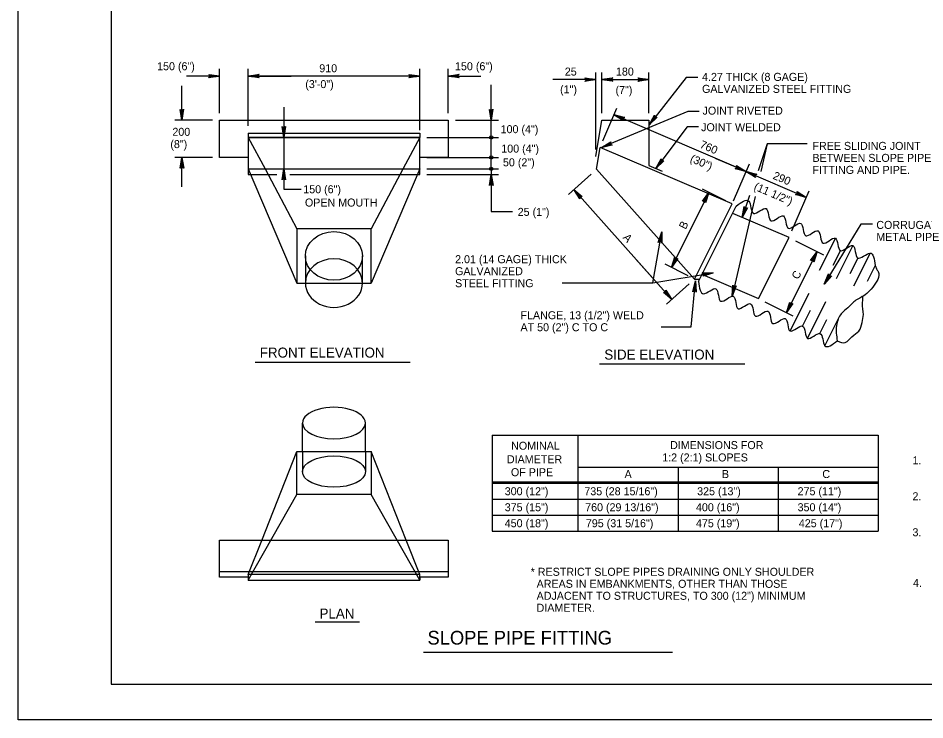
# Model space of a CAD drawing. Extents: x 637898 to 638802, y 298167 to 298761.
# Drawn here: x 637898 to 638278.7, y 298166.9 to 298461.7 of the extents above; entities that cross this region are included whole.
import ezdxf

# ---------------------------------------------------------------- set-up
doc = ezdxf.new("R2010")
doc.units = 0
for name, color, linetype in [('1', 7, 'Continuous'), ('2', 7, 'Continuous'), ('3', 7, 'Continuous'), ('PLT-BNDY', 7, 'Continuous')]:
    doc.layers.add(name, color=color, linetype=linetype)

msp = doc.modelspace()

# ---------------------------------------------------------------- linework, layer by layer
at = {"layer": '1'}
msp.add_lwpolyline([(638722.97, 298181.88), (638722.97, 298745.88), (637936.97, 298745.88), (637936.97, 298181.88), (638722.97, 298181.88), (638722.97, 298208.24), (638522.97, 298208.24), (638522.97, 298272.92), (638722.97, 298272.92), (638722.97, 298301.88), (638522.97, 298301.88), (638522.97, 298181.88), (638601.78, 298181.88), (638601.78, 298208.24), (638601.78, 298181.88), (638678.78, 298181.88), (638678.78, 298208.24), (638678.78, 298195.92), (638722.97, 298195.92)], dxfattribs=at)
at = {"layer": '2'}
for p, q in [((637982.59, 298421.79), (637982.59, 298440.37)), ((637994.59, 298416.39), (637994.59, 298440.37)), ((638066.59, 298414.59), (638066.59, 298440.37)), ((638078.59, 298421.79), (638078.59, 298440.37)), ((637982.59, 298437.37), (637968.69, 298437.37)), ((638048.59, 298437.37), (637994.59, 298437.37)), ((637994.59, 298437.37), (638012.59, 298437.37)), ((638066.59, 298437.37), (638047.46, 298437.37)), ((638066.59, 298437.37), (638048.59, 298437.37)), ((638078.59, 298437.37), (638092.3, 298437.37)), ((638140.55, 298435.88), (638122.55, 298435.88)), ((638140.55, 298435.88), (638125.07, 298435.88)), ((638140.55, 298406.55), (638140.55, 298438.88)), ((638143.07, 298421.79), (638143.07, 298438.88)), ((638143.07, 298435.88), (638162.87, 298435.88)), ((638162.87, 298421.79), (638162.87, 298438.88)), ((637966.75, 298418.79), (637966.75, 298433.2)), ((638096.62, 298418.79), (638096.62, 298433.65)), ((638096.62, 298411.59), (638096.62, 298429.59)), ((638009.54, 298424.25), (638009.54, 298411.59)), ((638096.62, 298403.19), (638096.62, 298421.19)), ((638143.53, 298410.15), (638149.44, 298423.86)), ((638205.38, 298396.5), (638148.25, 298421.11)), ((637979.59, 298418.79), (637963.75, 298418.79)), ((638081.59, 298418.79), (638099.62, 298418.79)), ((638140.55, 298403.55), (638143.07, 298418.79)), ((638143.07, 298418.79), (638162.87, 298418.79)), ((638162.87, 298418.79), (638162.87, 298399.8)), ((637994.59, 298413.39), (638066.59, 298413.39)), ((637994.59, 298413.39), (637994.59, 298411.59)), ((638066.59, 298413.39), (638066.59, 298411.59)), ((638096.62, 298398.39), (638096.62, 298416.39)), ((637994.59, 298411.59), (638066.59, 298411.59)), ((637994.59, 298411.59), (638001.64, 298398.33)), ((637997.59, 298411.59), (638012.54, 298411.59)), ((638009.54, 298411.59), (638009.54, 298398.39)), ((638066.59, 298411.59), (638059.64, 298398.5)), ((638069.59, 298411.59), (638099.62, 298411.59)), ((638140.83, 298398.18), (638142.35, 298407.4)), ((638197.79, 298383.64), (638142.35, 298407.4)), ((637979.59, 298403.19), (637963.75, 298403.19)), ((637966.75, 298390.85), (637966.75, 298403.19)), ((638069.59, 298403.19), (638099.62, 298403.19)), ((638203.62, 298397.26), (638190.79, 298402.79)), ((637994.59, 298398.39), (638066.59, 298398.39)), ((637994.59, 298398.39), (638014.99, 298350.39)), ((637997.59, 298398.39), (638012.54, 298398.39)), ((638001.64, 298398.33), (638014.99, 298373.19)), ((638009.54, 298398.39), (638009.54, 298389.79)), ((638059.64, 298398.5), (638046.19, 298373.19)), ((638066.59, 298398.39), (638046.19, 298350.39)), ((638069.59, 298398.39), (638099.62, 298398.39)), ((638140.83, 298398.18), (638182.06, 298352.07)), ((638162.87, 298399.8), (638168.47, 298397.4)), ((638198.33, 298384.91), (638205.02, 298400.51)), ((638069.59, 298395.99), (638099.62, 298395.99)), ((638138.59, 298396.18), (638129.05, 298387.64)), ((638203.62, 298397.25), (638228.96, 298386.39)), ((638009.54, 298389.79), (638016.83, 298389.79)), ((638131.28, 298389.64), (638172.52, 298343.54)), ((638188.02, 298388.5), (638172.29, 298356.94)), ((638195.1, 298384.97), (638185.33, 298389.84)), ((638222.91, 298372.27), (638230.14, 298389.15)), ((638181.95, 298351.96), (638197.79, 298383.64)), ((638183.72, 298351.07), (638199.56, 298382.75)), ((638199.56, 298382.75), (638199.56, 298382.75)), ((638206.84, 298379.63), (638206.84, 298379.63)), ((638206.84, 298379.63), (638206.84, 298379.63)), ((638214.12, 298376.51), (638214.12, 298376.51)), ((638214.12, 298376.51), (638214.12, 298376.51)), ((638046.19, 298373.19), (638014.99, 298373.19)), ((638014.99, 298373.19), (638014.99, 298350.39)), ((638046.19, 298350.39), (638046.19, 298373.19)), ((638221.4, 298373.39), (638221.4, 298373.39)), ((638224.41, 298368.18), (638236.15, 298362.3)), ((638228.68, 298370.27), (638228.68, 298370.27)), ((638241.16, 298369.23), (638234.39, 298355.7)), ((638233.47, 298363.65), (638220.64, 298337.99)), ((638235.96, 298367.15), (638235.96, 298367.15)), ((638243.24, 298364.03), (638240.09, 298357.73)), ((638248.44, 298366.11), (638241.46, 298352.17)), ((638243.24, 298364.03), (638243.24, 298364.03)), ((638018.59, 298361.79), (638018.59, 298350.39)), ((638042.59, 298350.39), (638042.59, 298361.79)), ((638157.26, 298360.59), (638172.52, 298343.54)), ((638250.52, 298360.91), (638247.16, 298354.2)), ((638255.72, 298362.99), (638248.74, 298349.04)), ((638250.52, 298360.91), (638250.52, 298360.91)), ((638179.37, 298353.41), (638169.61, 298358.28)), ((638257.8, 298357.79), (638254.44, 298351.08)), ((638257.8, 298357.79), (638257.8, 298357.79)), ((638182.06, 298352.07), (638184.2, 298352.03)), ((638014.99, 298350.39), (638046.19, 298350.39)), ((638179.82, 298350.07), (638170.28, 298341.54)), ((638183.72, 298351.07), (638183.72, 298351.07)), ((638222.2, 298330.27), (638230.13, 298346.14)), ((638205.56, 298341.71), (638205.56, 298341.71)), ((638211.58, 298342.51), (638223.32, 298336.64)), ((638229.48, 298327.15), (638237.2, 298342.61)), ((638212.84, 298338.59), (638212.84, 298338.59)), ((638227.4, 298332.35), (638230.71, 298338.99)), ((638220.12, 298335.47), (638220.12, 298335.47)), ((638234.68, 298329.23), (638237.6, 298335.08)), ((638236.76, 298324.03), (638242.38, 298335.27)), ((638227.4, 298332.35), (638227.4, 298332.35)), ((638234.68, 298329.23), (638234.68, 298329.23)), ((638241.96, 298326.11), (638241.96, 298326.11)), ((638017.39, 298279.59), (638017.39, 298291.59)), ((638043.79, 298279.59), (638043.79, 298291.59)), ((638000.24, 298242.28), (638014.99, 298279.59)), ((638014.99, 298279.59), (638046.19, 298279.59)), ((638014.99, 298261.59), (638014.99, 298279.59)), ((638017.39, 298279.59), (638017.39, 298271.19)), ((638043.79, 298279.59), (638043.79, 298271.19)), ((638046.19, 298279.59), (638046.19, 298261.59)), ((638060.92, 298242.33), (638046.19, 298279.59)), ((637994.59, 298225.59), (638014.99, 298261.59)), ((638046.19, 298261.59), (638014.99, 298261.59)), ((638066.59, 298225.59), (638046.19, 298261.59)), ((637994.59, 298227.99), (638000.24, 298242.28)), ((638066.59, 298227.99), (638060.9, 298242.39)), ((637982.59, 298229.19), (638078.59, 298229.19)), ((637994.59, 298227.99), (637994.59, 298226.79)), ((638066.59, 298226.79), (638066.59, 298225.59))]:
    msp.add_line(p, q, dxfattribs=at)
for points in [[(637978.23, 298437.89), (637978.39, 298437.58), (637982.59, 298437.37), (637978.23, 298437.89), (637978.01, 298438.08), (637982.59, 298437.37), (637978.4, 298437.14), (637978.25, 298436.83), (637982.59, 298437.37), (637978.01, 298436.62), (637978.25, 298436.83)], [(637998.96, 298436.85), (637998.79, 298437.17), (637994.59, 298437.37), (637998.96, 298436.85), (637999.18, 298436.67), (637994.59, 298437.37), (637998.78, 298437.61), (637998.94, 298437.92), (637994.59, 298437.37), (637999.17, 298438.13), (637998.94, 298437.92)], [(638062.23, 298437.89), (638062.39, 298437.58), (638066.59, 298437.37), (638062.23, 298437.89), (638062.01, 298438.08), (638066.59, 298437.37), (638062.4, 298437.14), (638062.25, 298436.83), (638066.59, 298437.37), (638062.01, 298436.62), (638062.25, 298436.83)], [(638082.96, 298436.85), (638082.79, 298437.17), (638078.59, 298437.37), (638082.96, 298436.85), (638083.18, 298436.67), (638078.59, 298437.37), (638082.78, 298437.61), (638082.94, 298437.92), (638078.59, 298437.37), (638083.17, 298438.13), (638082.94, 298437.92)], [(638136.19, 298436.4), (638136.36, 298436.09), (638140.55, 298435.88), (638136.19, 298436.4), (638135.97, 298436.59), (638140.55, 298435.88), (638136.36, 298435.65), (638136.21, 298435.33), (638140.55, 298435.88), (638135.98, 298435.12), (638136.21, 298435.33)], [(638147.43, 298435.36), (638147.27, 298435.68), (638143.07, 298435.88), (638147.43, 298435.36), (638147.66, 298435.17), (638143.07, 298435.88), (638147.26, 298436.12), (638147.41, 298436.43), (638143.07, 298435.88), (638147.65, 298436.64), (638147.41, 298436.43)], [(638158.51, 298436.4), (638158.67, 298436.09), (638162.87, 298435.88), (638158.51, 298436.4), (638158.28, 298436.59), (638162.87, 298435.88), (638158.68, 298435.65), (638158.53, 298435.33), (638162.87, 298435.88), (638158.29, 298435.12), (638158.53, 298435.33)], [(638183.35, 298436.75), (638178.55, 298436.75), (638162.94, 298416.92)], [(637967.27, 298423.16), (637966.95, 298422.99), (637966.75, 298418.79), (637967.27, 298423.16), (637967.46, 298423.38), (637966.75, 298418.79), (637966.51, 298422.99), (637966.2, 298423.14), (637966.75, 298418.79), (637965.99, 298423.37), (637966.2, 298423.14)], [(638097.14, 298423.16), (638096.83, 298422.99), (638096.62, 298418.79), (638097.14, 298423.16), (638097.33, 298423.38), (638096.62, 298418.79), (638096.39, 298422.99), (638096.07, 298423.14), (638096.62, 298418.79), (638095.87, 298423.37), (638096.07, 298423.14)], [(638183.93, 298422.5), (638179.13, 298422.5), (638142.91, 298407.29)], [(638152.05, 298418.89), (638152.02, 298419.25), (638148.25, 298421.11), (638152.05, 298418.89), (638152.18, 298418.63), (638148.25, 298421.11), (638152.19, 298419.65), (638152.46, 298419.88), (638148.25, 298421.11), (638152.76, 298419.98), (638152.46, 298419.88)], [(638166.06, 298420), (638165.71, 298420.07), (638162.94, 298416.92), (638166.06, 298420), (638166.35, 298420.06), (638162.94, 298416.92), (638165.37, 298420.34), (638165.22, 298420.65), (638162.94, 298416.92), (638165.2, 298420.97), (638165.22, 298420.65)], [(637994.59, 298403.19), (637982.59, 298403.19), (637982.59, 298418.79), (638078.59, 298418.79), (638078.59, 298403.19), (638066.59, 298403.19)], [(638010.06, 298415.96), (638009.75, 298415.79), (638009.54, 298411.59), (638010.06, 298415.96), (638010.25, 298416.18), (638009.54, 298411.59), (638009.31, 298415.79), (638008.99, 298415.94), (638009.54, 298411.59), (638008.79, 298416.17), (638008.99, 298415.94)], [(638183.66, 298415.96), (638178.86, 298415.96), (638165.8, 298398.54)], [(638012.02, 298395.99), (638066.59, 298395.99), (638066.59, 298411.59), (637994.59, 298411.59), (637994.59, 298403.19)], [(638147.14, 298408.47), (638146.87, 298408.7), (638142.91, 298407.29), (638147.14, 298408.47), (638147.42, 298408.38), (638142.91, 298407.29), (638146.7, 298409.1), (638146.72, 298409.45), (638142.91, 298407.29), (638146.85, 298409.74), (638146.72, 298409.45)], [(638229.37, 298408.83), (638217.37, 298408.83), (638212.57, 298408.83), (638208.72, 298397.57)], [(638212.57, 298408.83), (638209.91, 298397.32)], [(637966.23, 298398.83), (637966.55, 298399), (637966.75, 298403.19), (637966.23, 298398.83), (637966.04, 298398.61), (637966.75, 298403.19), (637966.98, 298399), (637967.3, 298398.85), (637966.75, 298403.19), (637967.51, 298398.61), (637967.3, 298398.85)], [(637994.59, 298403.19), (637994.59, 298395.99), (638006.65, 298395.99)], [(638168.85, 298401.7), (638168.5, 298401.76), (638165.8, 298398.54), (638168.85, 298401.7), (638169.14, 298401.77), (638165.8, 298398.54), (638168.15, 298402.02), (638167.99, 298402.33), (638165.8, 298398.54), (638167.97, 298402.65), (638167.99, 298402.33)], [(638205.38, 298396.5), (638191.04, 298402.65)], [(638009.02, 298394.03), (638009.34, 298394.2), (638009.54, 298398.39), (638009.02, 298394.03), (638008.83, 298393.81), (638009.54, 298398.39), (638009.78, 298394.2), (638010.09, 298394.05), (638009.54, 298398.39), (638010.3, 298393.81), (638010.09, 298394.05)], [(638096.62, 298398.39), (638096.62, 298395.99)], [(638199.83, 298399.47), (638199.86, 298399.11), (638203.62, 298397.25), (638199.83, 298399.47), (638199.7, 298399.73), (638203.62, 298397.25), (638199.69, 298398.71), (638199.42, 298398.48), (638203.62, 298397.25), (638199.12, 298398.39), (638199.42, 298398.48)], [(638096.1, 298391.63), (638096.42, 298391.8), (638096.62, 298395.99), (638096.1, 298391.63), (638095.91, 298391.41), (638096.62, 298395.99), (638096.86, 298391.8), (638097.17, 298391.65), (638096.62, 298395.99), (638097.38, 298391.41), (638097.17, 298391.65)], [(638096.62, 298395.99), (638096.62, 298380.39), (638105.62, 298380.39)], [(638207.42, 298395.04), (638207.39, 298395.39), (638203.62, 298397.25), (638207.42, 298395.04), (638207.55, 298394.77), (638203.62, 298397.25), (638207.56, 298395.8), (638207.83, 298396.02), (638203.62, 298397.25), (638208.13, 298396.12), (638207.83, 298396.02)], [(638133.78, 298386.03), (638133.9, 298386.36), (638131.28, 298389.64), (638133.78, 298386.03), (638133.78, 298385.73), (638131.28, 298389.64), (638134.23, 298386.65), (638134.56, 298386.75), (638131.28, 298389.64), (638134.88, 298386.71), (638134.56, 298386.75)], [(638185.58, 298384.85), (638185.94, 298384.85), (638188.02, 298388.5), (638185.58, 298384.85), (638185.31, 298384.73), (638188.02, 298388.5), (638186.33, 298384.66), (638186.54, 298384.38), (638188.02, 298388.5), (638186.62, 298384.08), (638186.54, 298384.38)], [(638207.45, 298386.69), (638197.79, 298344.9)], [(638205.15, 298387.15), (638202.01, 298377.97)], [(638225.17, 298388.61), (638225.19, 298388.25), (638228.96, 298386.39), (638225.17, 298388.61), (638225.04, 298388.87), (638228.96, 298386.39), (638225.03, 298387.85), (638224.76, 298387.62), (638228.96, 298386.39), (638224.46, 298387.53), (638224.76, 298387.62)], [(638203.94, 298381.91), (638203.59, 298381.86), (638202.01, 298377.97), (638203.94, 298381.91), (638204.19, 298382.06), (638202.01, 298377.97), (638203.17, 298382), (638202.93, 298382.25), (638202.01, 298377.97), (638202.81, 298382.54), (638202.93, 298382.25)], [(638185.31, 298353.96), (638208.9, 298343.86), (638221.73, 298369.52), (638198.14, 298379.62)], [(638256.71, 298375.13), (638251.91, 298375.13), (638236.49, 298349.91)], [(638126.44, 298350.48), (638164.46, 298350.48), (638168.33, 298371.86)], [(638167.01, 298367.67), (638167.35, 298367.77), (638168.33, 298371.86), (638167.01, 298367.67), (638166.79, 298367.48), (638168.33, 298371.86), (638167.79, 298367.7), (638168.07, 298367.49), (638168.33, 298371.86), (638168.23, 298367.22), (638168.07, 298367.49)], [(638231.03, 298359.99), (638231.39, 298359.99), (638233.47, 298363.65), (638231.03, 298359.99), (638230.76, 298359.88), (638233.47, 298363.65), (638231.78, 298359.8), (638231.99, 298359.52), (638233.47, 298363.65), (638232.07, 298359.22), (638231.99, 298359.52)], [(638174.73, 298360.59), (638174.37, 298360.59), (638172.29, 298356.94), (638174.73, 298360.59), (638175, 298360.71), (638172.29, 298356.94), (638173.98, 298360.78), (638173.77, 298361.06), (638172.29, 298356.94), (638173.69, 298361.36), (638173.77, 298361.06)], [(638164.46, 298350.48), (638189.89, 298354.72)], [(638185.5, 298354.54), (638185.72, 298354.26), (638189.89, 298354.72), (638185.5, 298354.54), (638185.25, 298354.7), (638189.89, 298354.72), (638185.79, 298353.83), (638185.69, 298353.49), (638189.89, 298354.72), (638185.49, 298353.25), (638185.69, 298353.49)], [(638239.23, 298353.34), (638238.88, 298353.37), (638236.49, 298349.91), (638239.23, 298353.34), (638239.51, 298353.43), (638236.49, 298349.91), (638238.5, 298353.59), (638238.32, 298353.89), (638236.49, 298349.91), (638238.26, 298354.2), (638238.32, 298353.89)], [(638167.94, 298332), (638180.64, 298332), (638182.38, 298351.26)], [(638181.45, 298346.96), (638181.77, 298347.1), (638182.38, 298351.26), (638181.45, 298346.96), (638181.23, 298346.76), (638182.38, 298351.26), (638182.21, 298347.06), (638182.51, 298346.88), (638182.38, 298351.26), (638182.7, 298346.63), (638182.51, 298346.88)], [(638199.3, 298349.02), (638198.96, 298348.94), (638197.79, 298344.9), (638199.3, 298349.02), (638199.54, 298349.2), (638197.79, 298344.9), (638198.53, 298349.03), (638198.26, 298349.25), (638197.79, 298344.9), (638198.11, 298349.53), (638198.26, 298349.25)], [(638170.02, 298347.15), (638169.9, 298346.82), (638172.52, 298343.54), (638170.02, 298347.15), (638170.02, 298347.45), (638172.52, 298343.54), (638169.57, 298346.53), (638169.24, 298346.43), (638172.52, 298343.54), (638168.92, 298346.47), (638169.24, 298346.43)], [(638223.08, 298341.64), (638222.72, 298341.64), (638220.64, 298337.99), (638223.08, 298341.64), (638223.35, 298341.76), (638220.64, 298337.99), (638222.33, 298341.83), (638222.11, 298342.11), (638220.64, 298337.99), (638222.03, 298342.41), (638222.11, 298342.11)], [(637994.59, 298226.79), (637982.59, 298226.79), (637982.59, 298242.39), (638078.59, 298242.39), (638078.59, 298226.79), (638066.59, 298226.79)]]:
    msp.add_lwpolyline(points, dxfattribs=at)
msp.add_lwpolyline([(637994.59, 298227.99), (637994.59, 298225.59), (638066.59, 298225.59), (638066.59, 298227.99)], close=True, dxfattribs=at)
for centre in [(638096.62, 298411.59), (638096.62, 298403.19), (638096.62, 298403.19), (638096.62, 298398.39)]:
    msp.add_circle(centre, 0.678, dxfattribs=at)
for centre, major_axis, ratio in [((638030.59, 298361.79), (-12, 0), 0.85), ((638030.59, 298271.19), (13.2, 0), 0.5)]:
    msp.add_ellipse(centre, major_axis=major_axis, ratio=ratio, dxfattribs=at)
for centre, major_axis, ratio, start_param, end_param in [((638030.59, 298350.39), (-12, 0), 0.85, 3.141593, 6.283185), ((638030.59, 298350.39), (-12, 0), 0.85, 0, 3.141593), ((638030.59, 298291.59), (13.2, 0), 0.5, 0, 3.141593), ((638030.59, 298291.59), (13.2, 0), 0.5, 3.141593, 6.283185)]:
    msp.add_ellipse(centre, major_axis=major_axis, ratio=ratio, start_param=start_param, end_param=end_param, dxfattribs=at)
for points in [[(638199.56, 298382.75), (638204.76, 298384.83), (638206.84, 298379.63), (638212.04, 298381.71), (638214.12, 298376.51), (638219.32, 298378.59), (638221.4, 298373.39), (638226.6, 298375.47), (638228.68, 298370.27), (638233.88, 298372.35), (638235.96, 298367.15), (638241.16, 298369.23), (638243.24, 298364.03), (638248.44, 298366.11), (638250.52, 298360.91), (638255.72, 298362.99), (638257.8, 298357.79)], [(638257.8, 298357.79), (638258.41, 298356.41), (638259.09, 298355.2), (638259.44, 298353.65), (638258.06, 298350.38), (638255.48, 298347.11), (638253.07, 298345.04), (638249.8, 298343.15), (638246.35, 298340.05), (638243.6, 298337.47), (638242.39, 298335.4), (638241.53, 298329.38), (638241.96, 298326.11)], [(638183.72, 298351.07), (638185.8, 298345.87), (638191, 298347.95), (638193.08, 298342.75), (638198.28, 298344.83), (638200.36, 298339.63), (638205.56, 298341.71), (638207.64, 298336.51), (638212.84, 298338.59), (638214.92, 298333.39), (638220.12, 298335.47), (638222.2, 298330.27), (638227.4, 298332.35), (638229.48, 298327.15), (638234.68, 298329.23), (638236.76, 298324.03), (638241.96, 298326.11)], [(638241.96, 298326.11), (638245.32, 298325.42), (638248.08, 298327.83), (638251, 298330.24), (638252.38, 298333.85), (638252.9, 298337.13), (638252.55, 298341.95), (638252.72, 298343.84), (638252.55, 298345.04)]]:
    msp.add_spline(points, degree=3, dxfattribs=at)
at = {"layer": '3'}
for p, q in [((637997.54, 298317.15), (638062.62, 298317.15)), ((638142.15, 298316.46), (638203.1, 298316.46)), ((638097.07, 298286.45), (638097.07, 298246.13)), ((638097.07, 298286.45), (638133.07, 298286.45)), ((638133.07, 298286.45), (638133.07, 298246.13)), ((638133.07, 298286.45), (638157.07, 298286.45)), ((638157.07, 298286.45), (638181.07, 298286.45)), ((638181.07, 298286.45), (638259.07, 298286.45)), ((638259.07, 298286.45), (638259.07, 298246.13)), ((638133.07, 298273.01), (638259.07, 298273.01)), ((638175.07, 298273.01), (638175.07, 298246.13)), ((638217.07, 298273.01), (638217.07, 298246.13)), ((638097.07, 298266.91), (638259.07, 298266.91)), ((638097.07, 298266.29), (638259.07, 298266.29)), ((638097.07, 298259.57), (638259.07, 298259.57)), ((638097.07, 298252.85), (638259.07, 298252.85)), ((638097.07, 298246.13), (638259.07, 298246.13)), ((638022.68, 298208), (638041.27, 298208)), ((638068.13, 298195.33), (638172.8, 298195.33))]:
    msp.add_line(p, q, dxfattribs=at)
at = {"layer": 'PLT-BNDY'}
msp.add_lwpolyline([(637897.97, 298760.88), (638738.97, 298760.88), (638738.97, 298166.88), (637897.97, 298166.88)], close=True, dxfattribs=at)

# ---------------------------------------------------------------- texts
at = {"layer": '1'}
for s, p in [('(1")', (638125.55, 298430.09)), ('(7")', (638148.83, 298429.83)), ('4.', (638273.74, 298222.73))]:
    msp.add_text(s, height=3.36, dxfattribs=at).set_placement(p)
at = {"layer": '3'}
for s, height, p in [('150 (6")', 3.36, (637956.33, 298439.8)), ('910', 3.36, (638024.43, 298438.95)), ('150 (6")', 3.36, (638081.43, 298439.8)), ('25', 3.36, (638127.53, 298437.56)), ('180', 3.36, (638149, 298437.56)), ('(3\'-0")', 3.36, (638018.55, 298432.3)), ('4.27 THICK (8 GAGE)', 3.36, (638185.16, 298435.33)), ('GALVANIZED STEEL FITTING', 3.36, (638185.16, 298430.29)), ('JOINT RIVETED', 3.36, (638185.37, 298421.15)), ('100 (4")', 3.36, (638100.58, 298413.36)), ('JOINT WELDED', 3.36, (638184.77, 298414.18)), ('200', 3.36, (637962.74, 298412.25)), ('(8")', 3.36, (637961.89, 298407.09)), ('FREE SLIDING JOINT', 3.36, (638231.52, 298406.34)), ('100 (4")', 3.36, (638100.86, 298405.2)), ('50 (2")', 3.36, (638101.56, 298399.44)), ('BETWEEN SLOPE PIPE', 3.36, (638231.52, 298401.3)), ('FITTING AND PIPE.', 3.36, (638231.52, 298396.26)), ('150 (6")', 3.36, (638017.71, 298388.12)), ('OPEN MOUTH', 3.36, (638018.41, 298382.54)), ('25 (1")', 3.36, (638107.75, 298378.62)), ('CORRUGATED', 3.36, (638258.34, 298373.14)), ('METAL PIPE', 3.36, (638258.34, 298368.1)), ('2.01 (14 GAGE) THICK', 3.36, (638081.46, 298358.74)), ('GALVANIZED', 3.36, (638081.46, 298353.7)), ('STEEL FITTING', 3.36, (638081.46, 298348.66)), ('FLANGE, 13 (1/2") WELD', 3.36, (638108.92, 298335.19)), ('AT 50 (2") C TO C', 3.36, (638108.92, 298330.15)), ('FRONT ELEVATION', 4.2, (637999.43, 298319.08)), ('SIDE ELEVATION', 4.2, (638144.12, 298318.26)), ('NOMINAL', 3.36, (638104.98, 298280.38)), ('DIMENSIONS FOR', 3.36, (638171.74, 298280.64)), ('DIAMETER', 3.36, (638103.21, 298274.69)), ('1:2 (2:1) SLOPES', 3.36, (638168.44, 298275.45)), ('1.  ', 3.36, (638273.53, 298274.26)), ('OF PIPE', 3.36, (638104.91, 298269.25)), ('A', 3.36, (638152.63, 298268.48)), ('B', 3.36, (638193.49, 298268.48)), ('C', 3.36, (638235.67, 298268.48)), ('300 (12")', 3.36, (638102.31, 298261.25)), ('735 (28 15/16")', 3.36, (638135.73, 298261.25)), ('325 (13")', 3.36, (638183.11, 298261.25)), ('275 (11")', 3.36, (638225.29, 298261.25)), ('2.  ', 3.36, (638273.53, 298259.14)), ('375 (15")', 3.36, (638102.31, 298254.53)), ('760 (29 13/16")', 3.36, (638136.08, 298254.53)), ('400 (16")', 3.36, (638182.6, 298254.53)), ('350 (14")', 3.36, (638225.29, 298254.53)), ('450 (18")', 3.36, (638102.31, 298247.81)), ('795 (31 5/16")', 3.36, (638136.38, 298247.81)), ('475 (19")', 3.36, (638182.6, 298247.81)), ('425 (17")', 3.36, (638225.8, 298247.81)), ('3.  ', 3.36, (638273.53, 298244.02)), ('* RESTRICT SLOPE PIPES DRAINING ONLY SHOULDER', 3.36, (638113.19, 298227.41)), ('  AREAS IN EMBANKMENTS, OTHER THAN THOSE', 3.36, (638113.19, 298222.37)), ('  ADJACENT TO STRUCTURES, TO 300 (12") MINIMUM', 3.36, (638113.19, 298217.33)), ('  DIAMETER.', 3.36, (638113.19, 298212.29)), ('PLAN', 4.2, (638024.52, 298209.46)), ('SLOPE PIPE FITTING', 5.76, (638069.86, 298198.52))]:
    msp.add_text(s, height=height, dxfattribs=at).set_placement(p)
for s, rotation, p in [('760', 336.6941, (638183.93, 298407.38)), ('(30")', 336.6941, (638179.84, 298401.49)), ('290', 336.8016, (638214.6, 298394.32)), ('(11 1/2")', 336.8016, (638206.63, 298389.73)), ('B', 63.5152, (638178.25, 298372.68)), ('A', 311.8055, (638151.7, 298369.33)), ('C', 63.435, (638225.59, 298351.65))]:
    msp.add_text(s, height=3.36, rotation=rotation, dxfattribs=at).set_placement(p)

doc.saveas('drawing.dxf')
